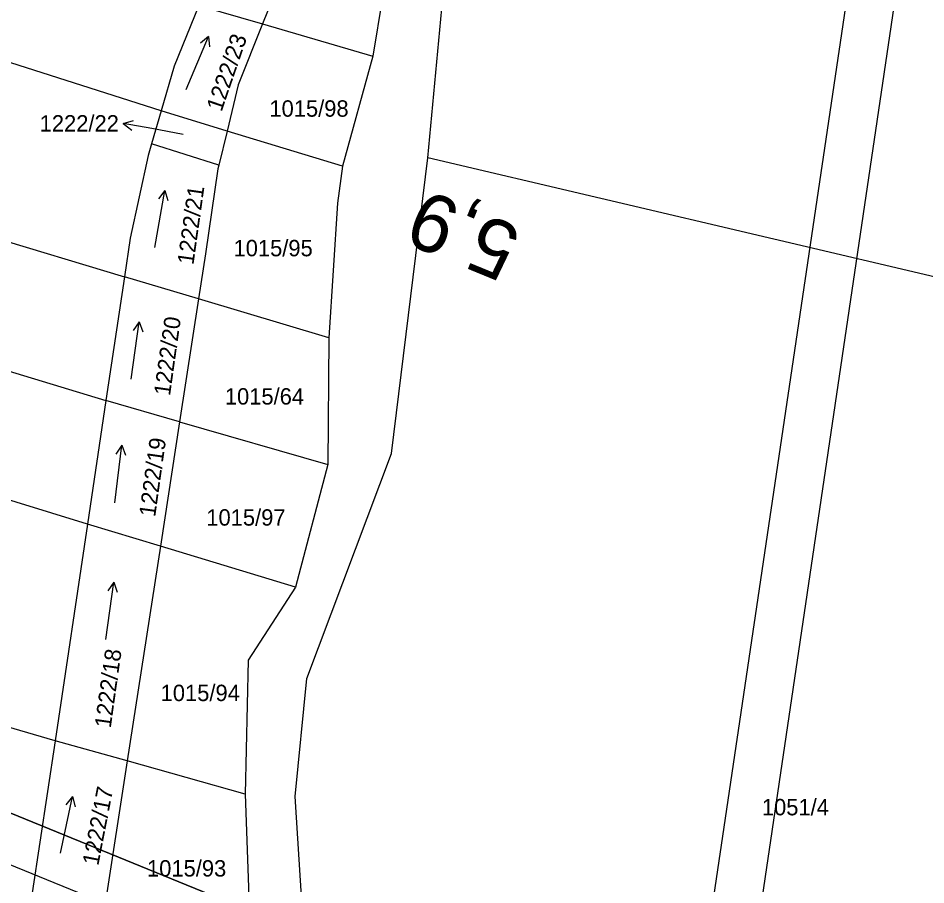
# Model space of a CAD drawing. Extents: x -779330 to -774454, y -1144748 to -1142831.
# Drawn here: x -776147.1 to -776053, y -1144378.3 to -1144288.4 of the extents above; entities that cross this region are included whole.
import ezdxf

# ---------------------------------------------------------------- set-up
doc = ezdxf.new("R2010")
doc.units = 0
for name, color, linetype in [('Hranice parcel', 7, 'Continuous'), ('Parcelní čísla', 7, 'Continuous'), ('Pop  PČ popisy', 7, 'Continuous'), ('Vrstva 1', 7, 'Continuous'), ('Vrstva 7', 7, 'Continuous'), ('Značky kultur', 7, 'Continuous')]:
    doc.layers.add(name, color=color, linetype=linetype)

msp = doc.modelspace()

# ---------------------------------------------------------------- linework, layer by layer
at = {"layer": 'Hranice parcel'}
for p, q in [((-776104.65, -1144302.9), (-776100.36, -1144257.59)), ((-776117.76, -1144278.93), (-776121.79, -1144289.01)), ((-776108.61, -1144281.88), (-776110.36, -1144292.35)), ((-776128.39, -1144287.08), (-776121.79, -1144289.01)), ((-776121.79, -1144289.01), (-776110.36, -1144292.35)), ((-776110.36, -1144292.35), (-776113.49, -1144303.76)), ((-776132.3, -1144298.01), (-776133.31, -1144301.45)), ((-776125.47, -1144300.13), (-776132.3, -1144298.01)), ((-776125.47, -1144300.13), (-776126.32, -1144303.67)), ((-776113.49, -1144303.76), (-776125.47, -1144300.13)), ((-776126.32, -1144303.67), (-776133.31, -1144301.45)), ((-775974.56, -1144333.51), (-776104.65, -1144302.9)), ((-776136.12, -1144315.24), (-776138.04, -1144328.07)), ((-776128.43, -1144317.53), (-776136.12, -1144315.24)), ((-776128.43, -1144317.53), (-776130.4, -1144330.27)), ((-776114.9, -1144321.56), (-776128.43, -1144317.53)), ((-776114.9, -1144321.56), (-776115.03, -1144334.7)), ((-776138.04, -1144328.07), (-776139.95, -1144340.89)), ((-776130.4, -1144330.27), (-776138.04, -1144328.07)), ((-776130.4, -1144330.27), (-776132.39, -1144343.18)), ((-776130.4, -1144330.27), (-776115.03, -1144334.7)), ((-776115.03, -1144334.7), (-776118.37, -1144347.43)), ((-776139.95, -1144340.89), (-776143.31, -1144363.37)), ((-776132.39, -1144343.18), (-776139.95, -1144340.89)), ((-776132.39, -1144343.18), (-776135.83, -1144365.45)), ((-776118.37, -1144347.43), (-776132.39, -1144343.18)), ((-776143.31, -1144363.37), (-776145.67, -1144379.15)), ((-776135.83, -1144365.45), (-776143.31, -1144363.37)), ((-776135.83, -1144365.45), (-776138.27, -1144381.26)), ((-776123.58, -1144368.89), (-776135.83, -1144365.45)), ((-776123.58, -1144368.89), (-776123.01, -1144385.62))]:
    msp.add_line(p, q, dxfattribs=at)
for points in [[(-776132.3, -1144298.01), (-776193.18, -1144278.57), (-776239.59, -1144263.48), (-776301.12, -1144240.48), (-776347.51, -1144219.6), (-776446.62, -1144176.16), (-776482.94, -1144162.91), (-776612.01, -1144123.26)], [(-776387.705, -1144222.254), (-776322.84, -1144252.89), (-776249.8, -1144280.91), (-776136.12, -1144315.24)], [(-776392.738, -1144234.565), (-776326.16, -1144265.8), (-776260.62, -1144289.93), (-776206.39, -1144307.32), (-776138.04, -1144328.07)], [(-776139.95, -1144340.89), (-776219.46, -1144316.38), (-776263.77, -1144302.5), (-776324.6, -1144278.51), (-776377.44, -1144254.65), (-776396.977, -1144244.936)], [(-776143.31, -1144363.37), (-776191.33, -1144349.34), (-776249.99, -1144330.39), (-776319.63, -1144305.99), (-776364.66, -1144287.25), (-776444.244, -1144249.735)], [(-776128.39, -1144287.08), (-776130.95, -1144293.39), (-776132.3, -1144298.01)], [(-776121.79, -1144289.01), (-776124.31, -1144295.31), (-776125.47, -1144300.13)], [(-776133.31, -1144301.45), (-776133.66, -1144302.64), (-776135.52, -1144311.24), (-776136.12, -1144315.24)], [(-776126.32, -1144303.67), (-776126.41, -1144304.03), (-776127.71, -1144312.84), (-776128.43, -1144317.53)], [(-775981.59, -1144370.37), (-776024.08, -1144381.29), (-776074.15, -1144417.28), (-776118.18, -1144455.2), (-776112.29, -1144427.95), (-776110.57, -1144410.43), (-776116.98, -1144391.49), (-776118.42, -1144369.14), (-776117.19, -1144356.92), (-776108.4, -1144333.55), (-776104.65, -1144302.9)], [(-776113.49, -1144303.76), (-776114.03, -1144307.59), (-776114.9, -1144321.56)], [(-776118.37, -1144347.43), (-776123.29, -1144355.01), (-776123.58, -1144368.89)]]:
    msp.add_lwpolyline(points, dxfattribs=at)
at = {"layer": 'Pop  PČ popisy'}
for p, q in [((-776136.235, -1144299.349), (-776135.162, -1144299.03)), ((-776133.28, -1144299.87), (-776136.235, -1144299.349)), ((-776136.235, -1144299.349), (-776135.336, -1144300.016)), ((-776130.02, -1144300.47), (-776133.28, -1144299.87))]:
    msp.add_line(p, q, dxfattribs=at)
at = {"layer": 'Vrstva 1'}
for points in [[(-775828.783, -1144506.701), (-776985.843, -1144033.744), (-776877.255, -1143768.09), (-775720.195, -1144241.047)], [(-775726.709, -1144243.781), (-776684.762, -1143852.169), (-776789.57, -1144108.576), (-775831.517, -1144500.187)], [(-775831.517, -1144500.187), (-776789.57, -1144108.576), (-776684.762, -1143852.169), (-775726.709, -1144243.781)], [(-774799.287, -1144366.036), (-776045.699, -1144181.555), (-776089.182, -1144475.344), (-774842.771, -1144659.826)], [(-774846.985, -1144654.148), (-776083.504, -1144471.13), (-776041.484, -1144187.233), (-774804.965, -1144370.25)]]:
    msp.add_lwpolyline(points, close=True, dxfattribs=at)
at = {"layer": 'Značky kultur'}
for p, q in [((-776129.728, -1144295.819), (-776127.383, -1144290.296)), ((-776127.383, -1144290.296), (-776128.227, -1144291)), ((-776127.383, -1144290.296), (-776127.303, -1144291.391)), ((-776132.97, -1144312.189), (-776131.928, -1144306.28)), ((-776131.928, -1144306.28), (-776132.591, -1144307.155)), ((-776131.928, -1144306.28), (-776131.604, -1144307.33)), ((-776135.417, -1144325.845), (-776134.582, -1144319.903)), ((-776134.582, -1144319.903), (-776135.214, -1144320.801)), ((-776134.582, -1144319.903), (-776134.221, -1144320.941)), ((-776137.105, -1144338.672), (-776136.374, -1144332.716)), ((-776136.374, -1144332.716), (-776136.991, -1144333.625)), ((-776136.374, -1144332.716), (-776135.995, -1144333.747)), ((-776138.047, -1144352.845), (-776137.212, -1144346.903)), ((-776137.212, -1144346.903), (-776137.844, -1144347.801)), ((-776137.212, -1144346.903), (-776136.851, -1144347.941)), ((-776142.752, -1144375.019), (-776141.504, -1144369.151)), ((-776141.504, -1144369.151), (-776142.198, -1144370.002)), ((-776141.504, -1144369.151), (-776141.217, -1144370.211))]:
    msp.add_line(p, q, dxfattribs=at)

# ---------------------------------------------------------------- texts
at = {"layer": 'Parcelní čísla'}
for s, rotation, p in [('1222/23', 71, (-776126.046, -1144298.186)), ('1222/21', 82, (-776128.958, -1144314.048)), ('1222/20', 82, (-776131.388, -1144327.638)), ('1222/19', 82, (-776132.928, -1144340.198)), ('1222/18', 82, (-776137.538, -1144362.108)), ('1222/17', 79, (-776138.825, -1144376.382))]:
    msp.add_text(s, height=1.7, rotation=rotation, dxfattribs=at).set_placement(p)
for s, p in [('1015/98', (-776121.08, -1144298.63)), ('1222/22', (-776144.906, -1144300.17)), ('1015/95', (-776124.8, -1144313.11)), ('1015/64', (-776125.7, -1144328.49)), ('1015/97', (-776127.62, -1144341.05)), ('1015/94', (-776132.36, -1144359.25)), ('1051/4', (-776070, -1144371.1)), ('1015/93', (-776133.77, -1144377.45))]:
    msp.add_text(s, height=1.7, dxfattribs=at).set_placement(p)
at = {"layer": 'Vrstva 7'}
msp.add_text('5,9', height=6, rotation=157.69402, dxfattribs=at).set_placement((-776094.695, -1144310.31))

doc.saveas('drawing.dxf')
